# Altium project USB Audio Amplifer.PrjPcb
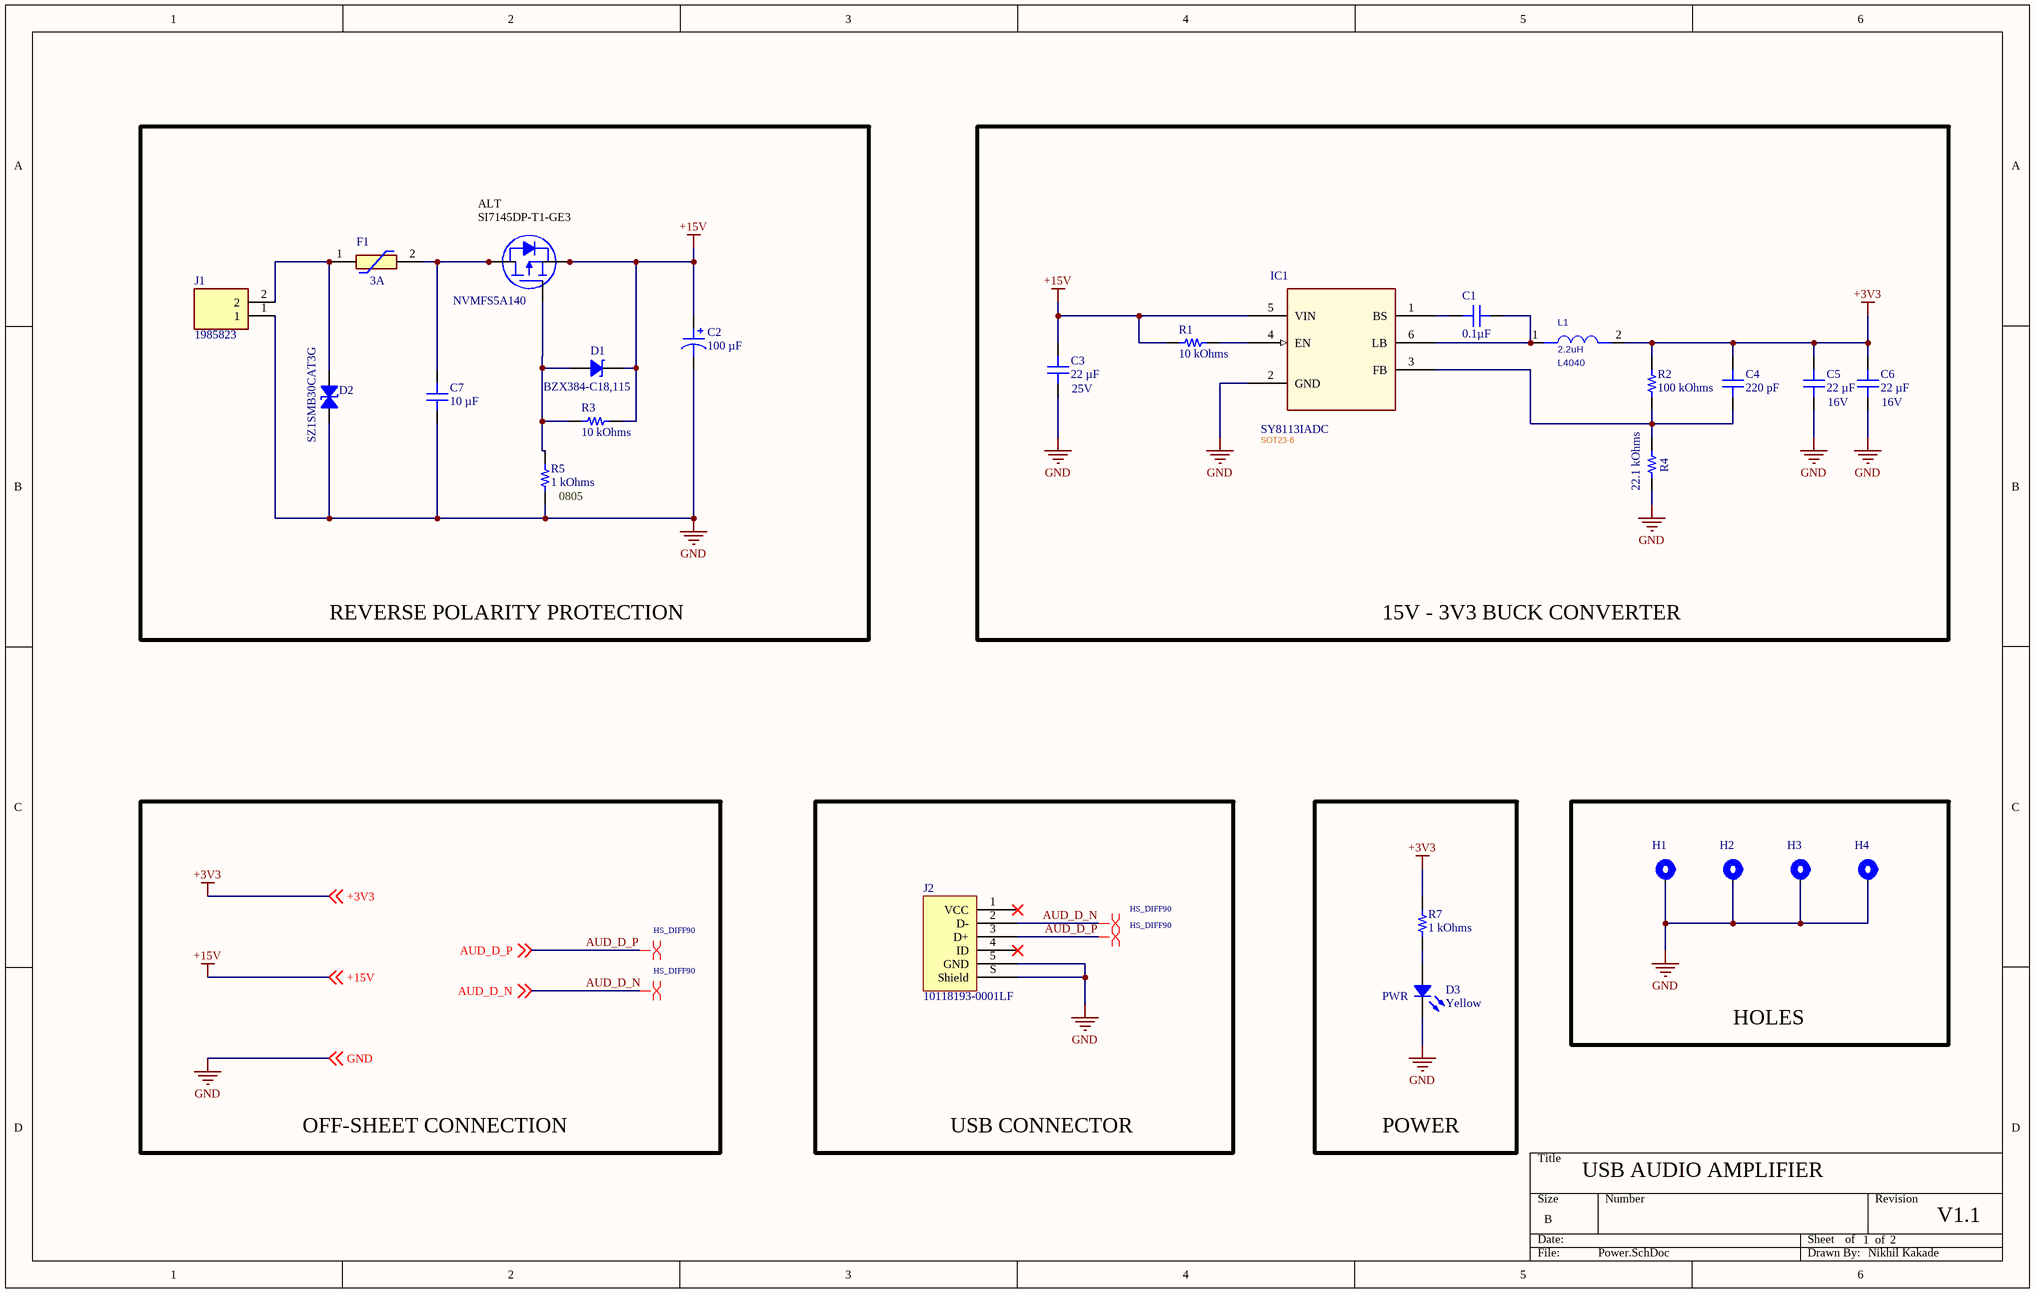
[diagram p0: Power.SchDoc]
2 sheets, 101 parts. Net scope: global (net labels, ports and power ports of the same name join across sheets).
Board file: PCB.PcbDoc
Sheets:
  Power.SchDoc
  Audio.SchDoc

## Sheet Power.SchDoc
size B; SheetNumber: 1; SheetTotal: 2

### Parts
C1  0.1µF  [CAP 0402_1005]
C2  100 µF  [CAP ALSMD 8.3MM H10.5MM]
C3  Voltage - Rated: 25V  [CAP 0805_2012]  (hidden comment: 22 µF)
C4  220 pF  [CAP 0402_1005]
C5  Voltage - Rated: 16V  [CAP 0805_2012]  (hidden comment: 22 µF)
C6  Voltage - Rated: 16V  [CAP 0805_2012]  (hidden comment: 22 µF)
C7  10 µF  [CAP 1206_3216 - 0.8MM]
D1  BZX384-C18,115  [SOD323]
D2  SZ1SMB30CAT3G  [DO214AA SMB]
D3  Yellow  [LED 0805_2012 YELLOW]
F1  3A  [1812L010DR]
H1  HOLE_4.1mm  [M2.0_3.6]  (value not drawn)
H2  HOLE_4.1mm  [M2.0_3.6]  (value not drawn)
H3  HOLE_4.1mm  [M2.0_3.6]  (value not drawn)
H4  HOLE_4.1mm  [M2.0_3.6]  (value not drawn)
IC1  SY8113IADC  [SOT23-6]
J1  1985823  [1985823]
J2  10118193-0001LF  [FCI USB 10118193-0001LF]
L1  2.2uH  [L4040]
Q1  NVMFS5A140  [NVMFS5A140PLZT1G]
R1  10 kOhms  [RES 0402_1005]
R2  100 kOhms  [RES 0402_1005]
R3  10 kOhms  [RES 0402_1005]
R4  22.1 kOhms  [RES 0402_1005]
R5  1 kOhms  Supplier Device Package: 0805  [RES 0805_2012]
R7  1 kOhms  [RES 0805_2012]

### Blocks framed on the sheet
REVERSE POLARITY PROTECTION: C2 C7 D1 D2 F1 J1 Q1 R3 R5
15V - 3V3 BUCK CONVERTER: C1 C3-C6 IC1 L1 R1 R2 R4
USB CONNECTOR: J2
POWER: D3 R7
HOLES: H1-H4

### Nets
+3V3: C4.2 C5.2 C6.2 L1.2 R2.1 R7.2 ; off-sheet +3V3
+15V: C2.1 C3.2 D1.2 IC1.5(VIN) Q1.1(S) Q1.2(S) Q1.3(S) R1.2 R3.2 ; off-sheet +15V
GND: C2.2 C3.1 C5.1 C6.1 C7.1 D2.1 D3.2 H1.1 H2.1 H3.1 H4.1 IC1.2(GND) J1.1 J2.5(GND) J2.S(Shield) R4.2 R5.1 ; off-sheet GND
AUD_D_N: J2.2(D-) ; off-sheet AUD_D_N
AUD_D_P: J2.3(D+) ; off-sheet AUD_D_P
NetC1_1: C1.1 IC1.1(BS)
NetC1_2: C1.2 IC1.6(LB) L1.1
NetC4_1: C4.1 IC1.3(FB) R2.2 R4.1
NetC7_2: C7.2 F1.2 Q1.5(D) Q1.6(D) Q1.7(D) Q1.8(D) Q1.9(D)
NetD1_1: D1.1 Q1.4(G) R3.1 R5.2
NetD2_2: D2.2 F1.1 J1.2
NetD3_1: D3.1 R7.1
NetIC1_4: IC1.4(EN) R1.1

Not connected (* = marked no-connect by the designer): J2 1(VCC)* 4(ID)*

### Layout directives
differential pair; differential pair class HS_DIFF90; net class HS_DIFF90: AUD_D_N, AUD_D_P

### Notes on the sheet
- (near Q1) ALT
  SI7145DP-T1-GE3
- (near D3) PWR
- OFF-SHEET CONNECTION
- USB AUDIO AMPLIFIER
- of
- V1.1
- Nikhil Kakade

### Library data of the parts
C1 = 0402YC104KAT2A: CAP CER 0.1UF 16V X7R 0402; manufacturer: AVX Corporation; Tolerance: ±10%
C2 = UWT1H101MNL1GS: CAP ALUM 100UF 20% 50V SMD; manufacturer: Nichicon; Lifetime @ Temp.: 1000 Hrs @ 105°C; Polarization: Polar; Ripple Current @ High Frequency: 210 mA @ 10 kHz; Ripple Current @ Low Frequency: 140 mA @ 120 Hz; Surface Mount Land Size: 0.327" L x 0.327" W (8.30mm x 8.30mm)
C3 C5 C6 = CL21A226MOCLRNC: CAP CER 22UF 16V X5R 0805; manufacturer: Samsung Electro-Mechanics; Tolerance: ±20%
C4 = 885012005063: CAP CER 220PF 50V C0G/NP0 0402; manufacturer: Würth Elektronik; Temperature Coefficient: C0G, NP0; Tolerance: ±5%
C7 = CL31B106KBHNNNE: CAP CER 10UF 50V X7R 1206; manufacturer: Samsung Electro-Mechanics; Tolerance: ±10%
D1 = DDZ9705S-7: DIODE ZENER 18V 200MW SOD323; Manufacturer: Diodes Incorporated; Current - Reverse Leakage @ Vr: 50 nA @ 13.6 V; Tolerance: ±5%; Voltage - Forward (Vf) (Max) @ If: 900 mV @ 10 mA
D2 = SZ1SMB30CAT3G: TVS DIODE 30VWM 48.4VC SMB; Manufacturer: Littelfuse Inc.; Bidirectional Channels: 1; Capacitance @ Frequency: 290pF @ 1MHz; Current - Peak Pulse (10/1000µs): 12.4A; Power Line Protection: No; Power - Peak Pulse: 600W; Type: Zener; Voltage - Breakdown (Min): 33.3V; Voltage - Clamping (Max) @ Ipp: 48.4V; Voltage - Reverse Standoff (Typ): 30V
D3 = VAOL-S8YP4: LED YELLOW CLEAR 0805 SMD; Manufacturer: Visual Communications Company - VCC; Configuration: Standard; Current - Test: 20mA; Lens Color: Colorless; Lens Size: 1.40mm x 1.25mm; Lens Style: Rectangle with Flat Top; Millicandela Rating: 92mcd; Viewing Angle: 140°; Voltage - Forward (Vf) (Typ): 2V; Wavelength - Dominant: 589nm; Wavelength - Peak: 591nm
F1 = 1812L150_12: Resettable Fuse; Manufacturer_Name: LITTELFUSE; Manufacturer_Part_Number: 1812L150/12
H1-H4 = HOLE_4mm: PART_NUMBER: PCB²âÊÔµã; Manufacturer: NA; Remarks: pcb
IC1 = MP1584_1
J1 = 1985823: Connector; Manufacturer_Name: Phoenix Contact
J2 = 10118193-0001LF: CONN RCPT USB2.0 MICRO B SMD R/A; Manufacturer: Amphenol ICC (FCI); Connector Type: USB - micro B; Current Rating (Amps): 1.8A per Contact; Gender: Receptacle; Mating Cycles: 10000; Number of Contacts: 5; Number of Ports: 1; Shielding: Shielded; Voltage - Rated: 100VAC
L1 = INDUCTOR_Dup1_1: PART_NUMBER: FDSD0420D-1R0M
Q1 = NVMFS5A140PLZ: Single P-Channel Power MOSFET, -40 V, -140 A; Part Number: BSZ067N06LS3GATMA1; Manufacturer: Infineon Technologies; Current - Continuous Drain (Id) @ 25°C: 14A (Ta), 20A (Tc); Drain to Source Voltage (Vdss): 60V; Drive Voltage (Max Rds On,  Min Rds On): 4.5V, 10V; FET Type: N-Channel; Gate Charge (Qg) (Max) @ Vgs: 67nC @ 10V; Input Capacitance (Ciss) (Max) @ Vds: 5100pF @ 30V; Power Dissipation (Max): 2.1W (Ta), 69W (Tc); Rds On (Max) @ Id, Vgs: 6.7mOhm @ 20A, 10V; Vgs (Max): ±20V; Vgs(th) (Max) @ Id: 2.2V @ 35µA
R1 R3 = CRG0402F10K: RES SMD 10K OHM 1% 1/16W 0402; Manufacturer: TE Connectivity Passive Product; Power (Watts): 0.063W, 1/16W; Temperature Coefficient: ±100ppm/°C
R2 = RC0402FR-07453KL: RES 453K OHM 1% 1/16W 0402; Manufacturer: Yageo; Power (Watts): 0.063W, 1/16W; Resistance: 453 kOhms; Temperature Coefficient: ±100ppm/°C
R4 = RCG0402100KFKED: RES SMD 100K OHM 1% 1/16W 0402; Manufacturer: Vishay Dale; Power (Watts): 0.063W, 1/16W; Resistance: 100 kOhms; Temperature Coefficient: ±100ppm/°C
R5 R7 = SR0805JR-7W1KL: RES 1K OHM 5% 1/4W 0805; Manufacturer: Yageo; Power (Watts): 0.25W, 1/4W; Temperature Coefficient: ±100ppm/°C

## Sheet Audio.SchDoc
size Tabloid; SheetNumber: 2; SheetTotal: 2
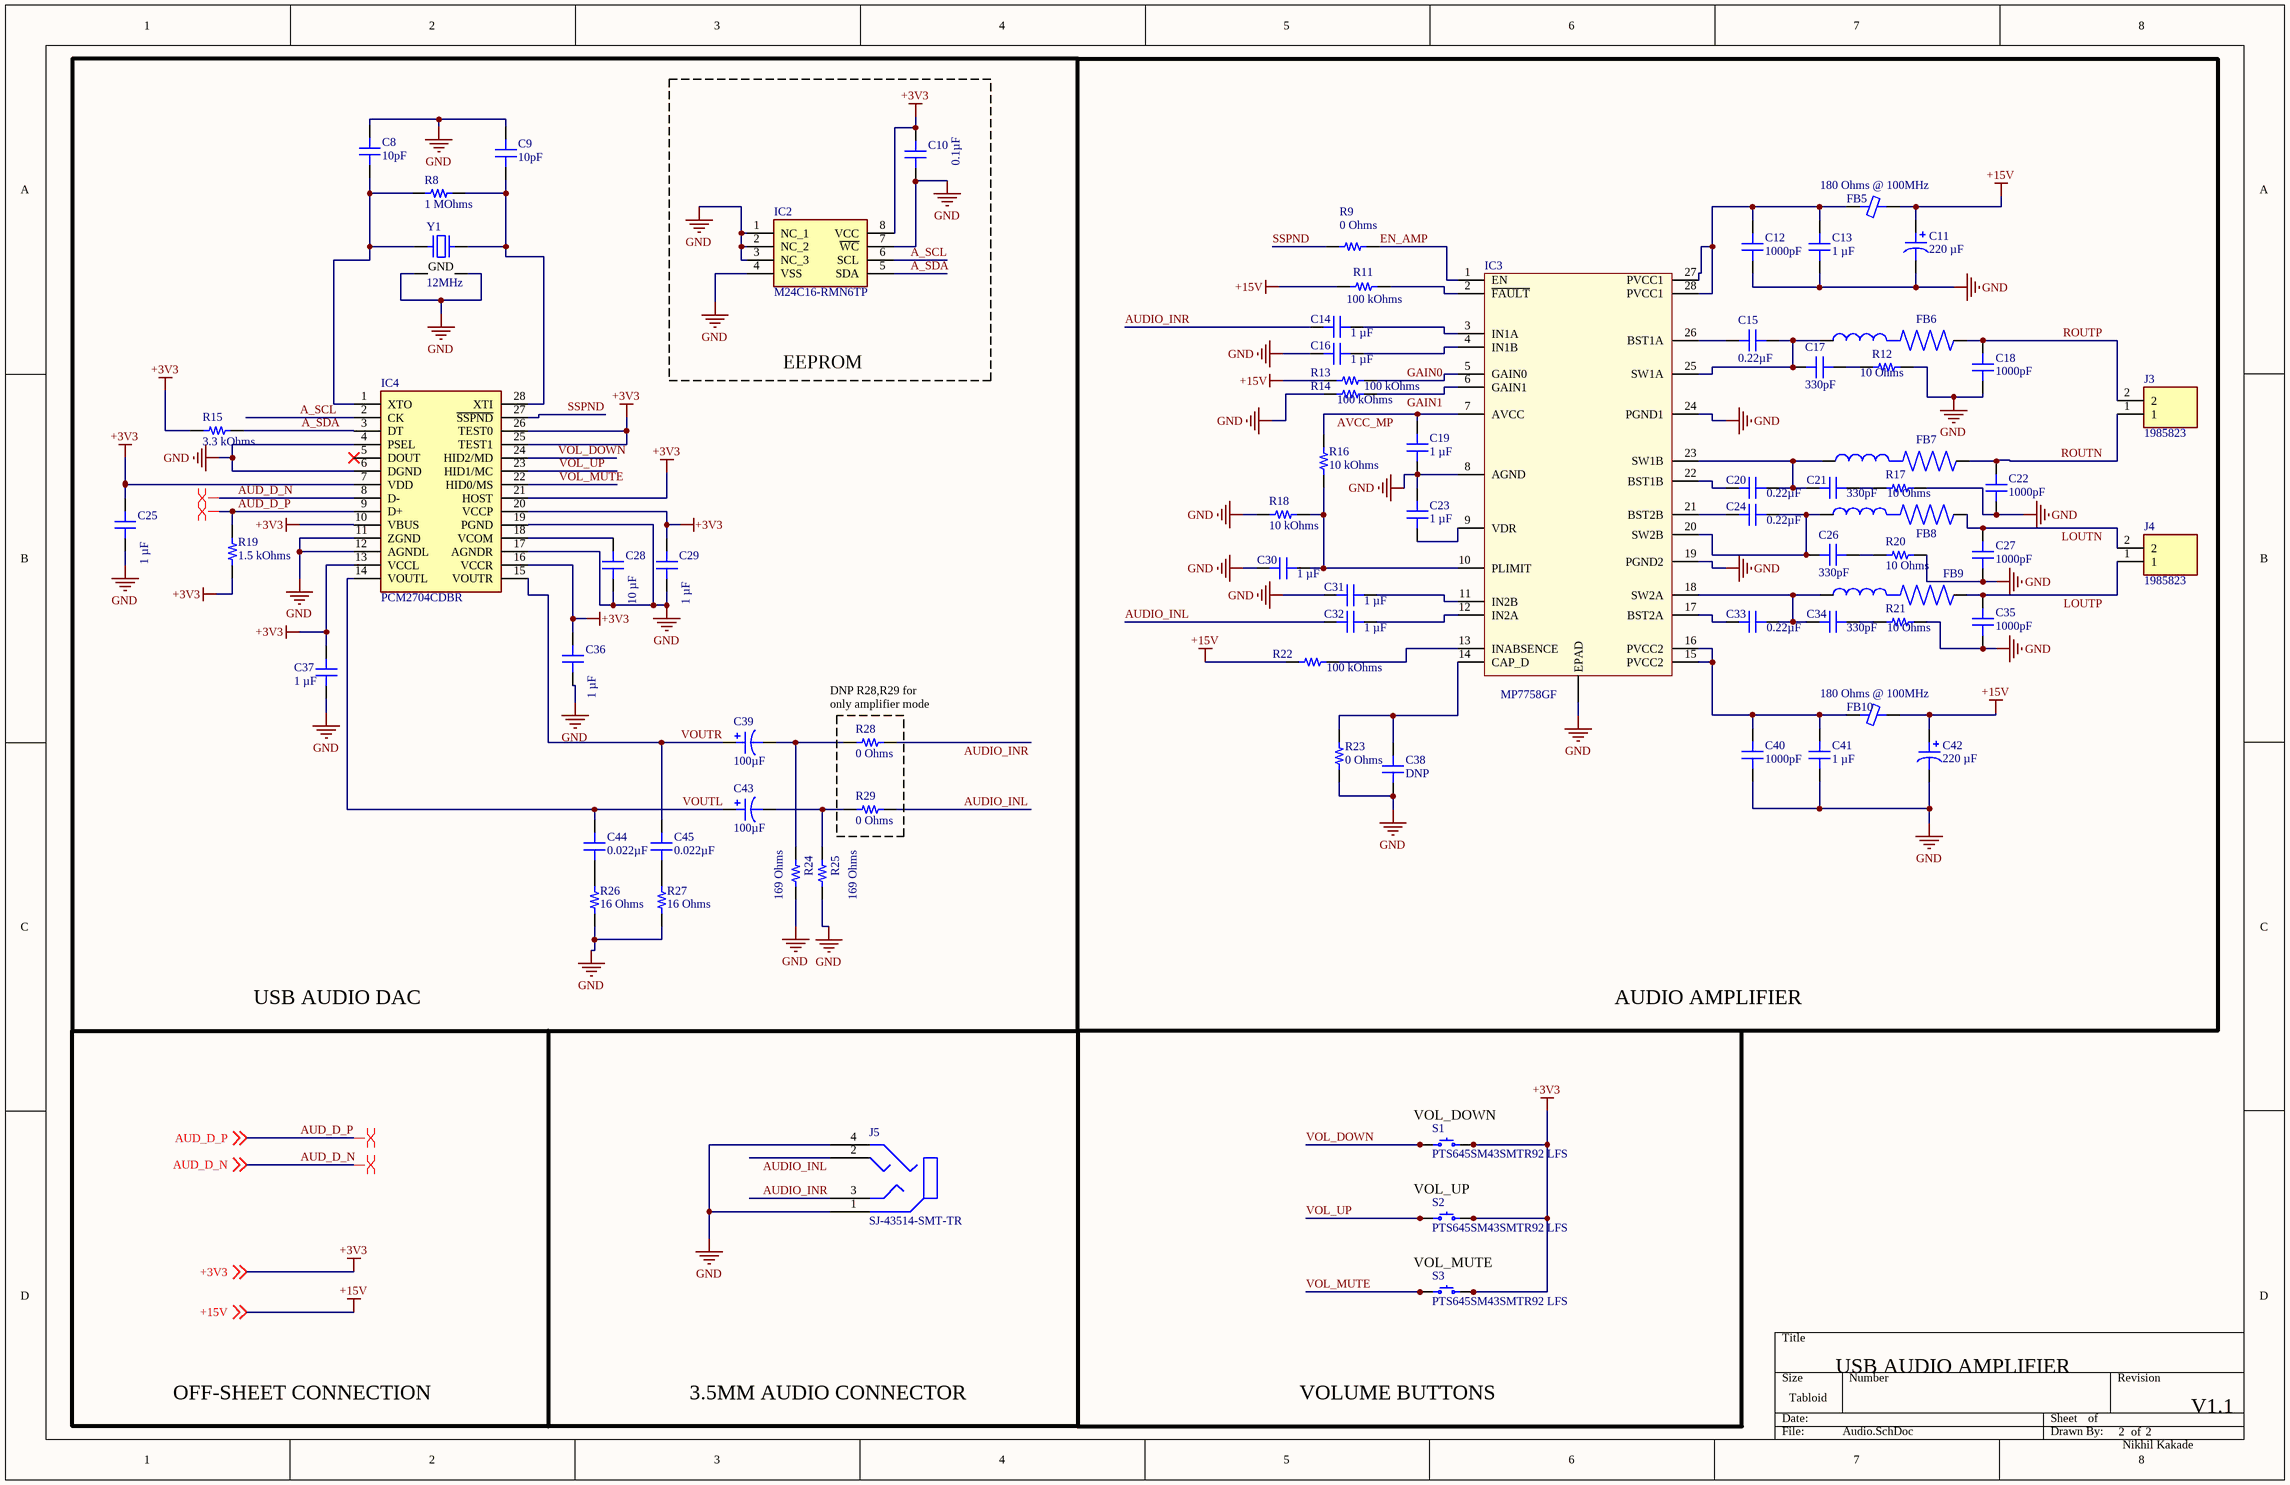
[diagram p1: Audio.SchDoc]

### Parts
C8  10pF  [CAP 0402_1005]
C9  10pF  [CAP 0402_1005]
C10  0.1µF  [CAP 0402_1005]
C11  220 µF  [CAP ALSMD 8.3MM H10.5MM]
C12  1000pF  [CAP 0402_1005]
C13  1 µF  [CAP 0603_1608]
C14  1 µF  [CAP 0603_1608]
C15  0.22µF  [CAP 0402_1005]
C16  1 µF  [CAP 0603_1608]
C17  330pF  [CAP 0402_1005]
C18  1000pF  [CAP 0402_1005]
C19  1 µF  [CAP 0603_1608]
C20  0.22µF  [CAP 0402_1005]
C21  330pF  [CAP 0402_1005]
C22  1000pF  [CAP 0402_1005]
C23  1 µF  [CAP 0603_1608]
C24  0.22µF  [CAP 0402_1005]
C25  1 µF  [CAP 0603_1608]
C26  330pF  [CAP 0402_1005]
C27  1000pF  [CAP 0402_1005]
C28  10 µF  [CAP 1206_3216 - 0.8MM]
C29  1 µF  [CAP 0603_1608]
C30  1 µF  [CAP 0603_1608]
C31  1 µF  [CAP 0603_1608]
C32  1 µF  [CAP 0603_1608]
C33  0.22µF  [CAP 0402_1005]
C34  330pF  [CAP 0402_1005]
C35  1000pF  [CAP 0402_1005]
C36  1 µF  [CAP 0603_1608]
C37  1 µF  [CAP 0603_1608]
C38  DNP  [CAP 0402_1005]
C39  100µF  [CAP POL 1411_3528]
C40  1000pF  [CAP 0402_1005]
C41  1 µF  [CAP 0603_1608]
C42  220 µF  [CAP ALSMD 8.3MM H10.5MM]
C43  100µF  [CAP POL 1411_3528]
C44  0.022µF  [CAP 0402_1005]
C45  0.022µF  [CAP 0402_1005]
FB5  180 Ohms @ 100MHz  [FER 0805_2012]
FB6  NFZ2MSM601SN10L  [BEADC2016X100N]  (value not drawn)
FB7  NFZ2MSM601SN10L  [BEADC2016X100N]  (value not drawn)
FB8  NFZ2MSM601SN10L  [BEADC2016X100N]  (value not drawn)
FB9  NFZ2MSM601SN10L  [BEADC2016X100N]  (value not drawn)
FB10  180 Ohms @ 100MHz  [FER 0805_2012]
IC2  M24C16-RMN6TP  [SOIC127P600X175-8N]
IC3  MP7758GF  [MP7758GF]
IC4  PCM2704CDBR  [SOP65P780X200-28N]
J3  1985823  [1985823]
J4  1985823  [1985823]
J5  SJ-43514-SMT-TR  [CUI SJ-43514-SMT-TR]
R8  1 MOhms  [RES 0603_1608]
R9  0 Ohms  [RES 0402_1005]
R11  100 kOhms  [RES 0402_1005]
R12  10 Ohms  [RES 0402_1005]
R13  100 kOhms  [RES 0402_1005]
R14  100 kOhms  [RES 0402_1005]
R15  3.3 kOhms  [RES 0402_1005]
R16  10 kOhms  [RES 0402_1005]
R17  10 Ohms  [RES 0402_1005]
R18  10 kOhms  [RES 0402_1005]
R19  1.5 kOhms  [RES 0402_1005]
R20  10 Ohms  [RES 0402_1005]
R21  10 Ohms  [RES 0402_1005]
R22  100 kOhms  [RES 0402_1005]
R23  0 Ohms  [RES 0402_1005]
R24  169 Ohms  [RES 0402_1005]
R25  169 Ohms  [RES 0402_1005]
R26  16 Ohms  [RES 0402_1005]
R27  16 Ohms  [RES 0402_1005]
R28  0 Ohms  [RES 0402_1005]
R29  0 Ohms  [RES 0402_1005]
S1  PTS645SM43SMTR92 LFS  [C&K PTS645]
S2  PTS645SM43SMTR92 LFS  [C&K PTS645]
S3  PTS645SM43SMTR92 LFS  [C&K PTS645]
Y1  12MHz  [ABRACON ABM8G]

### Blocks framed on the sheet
USB AUDIO DAC: C8 C9 C25 C28 C29 C36 C37 C39 C43-C45 IC4 R8 R15 R19 R24-R29 Y1
EEPROM: C10 IC2

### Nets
+3V3: C10.2 C25.2 C29.2 C36.2 C37.2 IC2.8(VCC) IC4.7(VDD) IC4.10(VBUS) IC4.13(VCCL) IC4.16(VCCR) IC4.20(VCCP) IC4.21(HOST) IC4.25(TEST1) IC4.26(TEST0) R15.1 R19.1 S1.3 S1.4 S2.3 S2.4 S3.3 S3.4 ; off-sheet +3V3
+15V: C11.1 C42.1 FB5.2 FB10.2 R11.2 R13.2 R22.2 ; off-sheet +15V
GND: C8.2 C9.2 C10.1 C11.2 C12.1 C13.1 C16.1 C18.1 C19.1 C22.1 C23.2 C25.1 C27.1 C28.1 C29.1 C30.1 C31.1 C35.1 C36.1 C37.1 C38.1 C40.1 C41.1 C42.2 IC2.1(NC_1) IC2.2(NC_2) IC2.3(NC_3) IC2.4(VSS) IC2.7(~{WC}) IC3.8(AGND) IC3.19(PGND2) IC3.24(PGND1) IC3.EPAD IC4.4(PSEL) IC4.6(DGND) IC4.11(ZGND) IC4.12(AGNDL) IC4.17(AGNDR) IC4.19(PGND) J5.1(SLEEVE) J5.4(RING_2) R12.2 R14.2 R17.2 R18.2 R20.1 R21.2 R23.1 R24.1 R25.1 R26.1 R27.1 Y1.2(GND) Y1.4(GND)
A_SCL: IC2.6(SCL) IC4.2(CK)
A_SDA: IC2.5(SDA) IC4.3(DT) R15.2
AUD_D_N: IC4.8(D-) ; off-sheet AUD_D_N
AUD_D_P: IC4.9(D+) R19.2 ; off-sheet AUD_D_P
AUDIO_INL: C32.1 J5.2(TIP) R29.1
AUDIO_INR: C14.1 J5.3(RING_1) R28.1
AVCC_MP: C19.2 IC3.7(AVCC) R16.1
EN_AMP: IC3.1(EN) R9.1
GAIN0: IC3.5(GAIN0) R13.1
GAIN1: IC3.6(GAIN1) R14.1
LOUTN: C27.2 FB8.2 J4.2
LOUTP: C35.2 FB9.2 J4.1
ROUTN: C22.2 FB7.2 J3.1
ROUTP: C18.2 FB6.2 J3.2
SSPND: IC4.27(~{SSPND}) R9.2
VOL_DOWN: IC4.24(HID2/MD) S1.1 S1.2
VOL_MUTE: IC4.22(HID0/MS) S3.1 S3.2
VOL_UP: IC4.23(HID1/MC) S2.1 S2.2
VOUTL: C43.1 C44.2 IC4.14(VOUTL)
VOUTR: C39.1 C45.2 IC4.15(VOUTR)
NetC8_1: C8.1 IC4.1(XTO) R8.1 Y1.1
NetC9_1: C9.1 IC4.28(XTI) R8.2 Y1.3
NetC12_2: C12.2 C13.2 FB5.1 IC3.27(PVCC1) IC3.28(PVCC1)
NetC14_2: C14.2 IC3.3(IN1A)
NetC15_1: C15.1 IC3.26(BST1A)
NetC15_2: C15.2 C17.1 FB6.1 IC3.25(SW1A)
NetC16_2: C16.2 IC3.4(IN1B)
NetC17_2: C17.2 R12.1
NetC20_1: C20.1 IC3.22(BST1B)
NetC20_2: C20.2 C21.1 FB7.1 IC3.23(SW1B)
NetC21_2: C21.2 R17.1
NetC23_1: C23.1 IC3.9(VDR)
NetC24_1: C24.1 IC3.21(BST2B)
NetC24_2: C24.2 C26.1 FB8.1 IC3.20(SW2B)
NetC26_2: C26.2 R20.2
NetC28_2: C28.2 IC4.18(VCOM)
NetC30_2: C30.2 IC3.10(PLIMIT) R16.2 R18.1
NetC31_2: C31.2 IC3.11(IN2B)
NetC32_2: C32.2 IC3.12(IN2A)
NetC33_1: C33.1 IC3.17(BST2A)
NetC33_2: C33.2 C34.1 FB9.1 IC3.18(SW2A)
NetC34_2: C34.2 R21.1
NetC38_2: C38.2 IC3.14(CAP_D) R23.2
NetC39_2: C39.2 R24.2 R28.2
NetC40_2: C40.2 C41.2 FB10.1 IC3.15(PVCC2) IC3.16(PVCC2)
NetC43_2: C43.2 R25.2 R29.2
NetC44_1: C44.1 R26.2
NetC45_1: C45.1 R27.2
NetIC3_2: IC3.2(~{FAULT}) R11.1
NetIC3_13: IC3.13(INABSENCE) R22.1

Not connected (* = marked no-connect by the designer): IC4 5(DOUT)*

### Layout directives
differential pair; differential pair class HS_DIFF90; net class HS_DIFF90: AUD_D_N, AUD_D_P

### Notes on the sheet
- (near R28) DNP R28,R29 for only amplifier mode
- AUDIO AMPLIFIER
- (near S1) VOL_DOWN
- (near S2) VOL_UP
- (near S3) VOL_MUTE
- USB AUDIO AMPLIFIER
- OFF-SHEET CONNECTION
- 3.5MM AUDIO CONNECTOR
- VOLUME BUTTONS
- of
- V1.1
- Nikhil Kakade

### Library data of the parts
C8 C9 = GJM1555C1H300FB01D: CAP CER 10PF 50V C0G/NP0 0402; Manufacturer: Murata Electronics; Capacitance: 30pF; Temperature Coefficient: C0G, NP0; Tolerance: ±1%
C10 = 0402YC104KAT2A: as C1 on sheet Power
C11 C42 = EEE-FK1V221GP: CAP ALUM 220UF 20% 35V SMD; manufacturer: Panasonic Electronic Components; Lifetime @ Temp.: 5000 Hrs @ 105°C; Polarization: Polar; Ripple Current @ High Frequency: 600 mA @ 100 kHz; Ripple Current @ Low Frequency: 450 mA @ 120 Hz; Surface Mount Land Size: 0.327" L x 0.327" W (8.30mm x 8.30mm); Impedance: 160 mOhms
C12 C18 C22 C27 C35 C38 C40 = 04025C102KAT4A: CAP CER 1000PF 50V X7R 0402; Manufacturer: AVX Corporation; Tolerance: ±10%
C13 C14 C16 C19 C23 C25 C29-C32 C36 C37 C41 = C0603C105K4RACAUTO: CAP CER 0603 1UF 16V X7R 10%
C15 C20 C24 C33 = CL05B224KO5NNNC: CAP CER 0.22UF 16V X7R 0402; Manufacturer: Samsung Electro-Mechanics; Tolerance: ±10%
C17 C21 C26 C34 = CC0402JRX7R9BB331: CAP CER 330PF 50V X7R 0402; Manufacturer: Yageo; Tolerance: ±5%
C28 = CL31B106KBHNNNE: as C7 on sheet Power
C39 C43 = F931A107KBA: CAP TANT 100UF 10% 10V 1411; Manufacturer: AVX Corporation; Manufacturer Size Code: B; ESR (Equivalent Series Resistance): 1.2Ohm @ 100kHz; Lifetime @ Temp.: 2000 Hrs @ 125°C; Type: Molded
C44 C45 = CL05B223KP5NNNC: CAP CER 0.022UF 10V X7R 0402; Manufacturer: Samsung Electro-Mechanics; Tolerance: ±10%
FB5 FB10 = 74279220181: FERRITE BEAD 180 OHM 0805 1LN; Manufacturer: Würth Elektronik; Current Rating (Max): 4A; DC Resistance (DCR) (Max): 37mOhm; Number of Lines: 1
FB6-FB9 = NFZ2MSM601SN10L: Ferrite Beads Multi-Layer 600Ohm 25% 100MHz 2.5A 46mOhm DCR 0806 Automotive T/R; MF: {'manufacturer': u'Murata Electronics'}
IC2 = M24C16-RMN6TP: Integrated Circuit; Manufacturer_Name: STMicroelectronics
IC3 = MP7758GF: Amplifier IC 2-Channel (Stereo) Class D 28-TSSOP-EP; Manufacturer: Monolithic Power Systems Inc.; Part Number: MP7758GF-Z
IC4 = PCM2704CDBR: Integrated Circuit; Manufacturer_Name: Texas Instruments
J3 J4 = 1985823: as J1 on sheet Power
J5 = SJ-43514-SMT-TR: CONN JACK 4COND 3.5MM SMD R/A; Manufacturer: CUI Devices; Actual Diameter: 0.142" (3.60mm); Connector Type: Phone Jack; Gender: Female; Industry Recognized Mating Diameter: 3.50mm (0.141", 1/8", Mini Plug) - Headphone; Internal Switch(s): Does Not Contain Switch; Number of Positions/Contacts: 4 Conductors, 4 Contacts; Shielding: Unshielded; Signal Lines: Stereo (4 Conductor, TRRS)
R8 = RMCF0603JT1M00: RES 1M OHM 5% 1/10W 0603; Manufacturer: Stackpole Electronics Inc; Power (Watts): 0.1W, 1/10W; Temperature Coefficient: ±200ppm/°C
R9 R23 R28 R29 = JR0402X20E: 0402 20 AMP JUMPER; Manufacturer: Ohmite; Power (Watts): 0.2W, 1/5W
R11 R13 R14 R22 = RCG0402100KFKED: RES SMD 100K OHM 1% 1/16W 0402; Manufacturer: Vishay Dale; Power (Watts): 0.063W, 1/16W; Temperature Coefficient: ±100ppm/°C
R12 R17 R20 R21 = RMCF0402FT10R0: RES 10 OHM 1% 1/16W 0402; Manufacturer: Stackpole Electronics Inc; Power (Watts): 0.063W, 1/16W; Temperature Coefficient: ±100ppm/°C
R15 = RMCF0402FT3K30: RES 3.3K OHM 1% 1/16W 0402; Manufacturer: Stackpole Electronics Inc; Power (Watts): 0.063W, 1/16W; Temperature Coefficient: ±100ppm/°C
R16 R18 = CRG0402F10K: as R1 on sheet Power
R19 = CRCW04021K50FKEDHP: RES SMD 1.5K OHM 1% 1/5W 0402
R24 R25 = RK73H1ETTP1690F: RES 169 OHM 1% 1/10W 0402; Manufacturer: KOA Speer Electronics, Inc.; Power (Watts): 0.1W, 1/10W; Temperature Coefficient: ±100ppm/°C
R26 R27 = ERJ-2RKF16R0X: RES SMD 16 OHM 1% 1/10W 0402; Manufacturer: Panasonic Electronic Components; Power (Watts): 0.1W, 1/10W; Temperature Coefficient: ±100ppm/°C
S1-S3 = PTS645SM43SMTR92 LFS: SWITCH TACTILE SPST-NO 0.05A 12V; Manufacturer: C&K; Actuator Height off PCB, Vertical: 4.30mm; Actuator Orientation: Top Actuated; Actuator Type: Standard; Contact Rating @ Voltage: 0.05A @ 12VDC; Illumination: Non-Illuminated; Operating Force: 160gf; Outline: 6.00mm x 6.00mm; Switch Function: Off-Mom
Y1 = ABM8G-12.000MHZ-B4Y-T: CRYSTAL 12.0000MHZ 10PF SMD; Manufacturer: Abracon LLC; ESR (Equivalent Series Resistance): 120 Ohms; Frequency Stability: ±30ppm; Operating Mode: Fundamental

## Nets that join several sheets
+3V3: Power (6 pins), Audio (22 pins)
+15V: Power (9 pins), Audio (7 pins)
GND: Power (17 pins), Audio (54 pins)
AUD_D_N: Power (J2.2), Audio (IC4.8)
AUD_D_P: Power (J2.3), Audio (IC4.9 R19.2)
